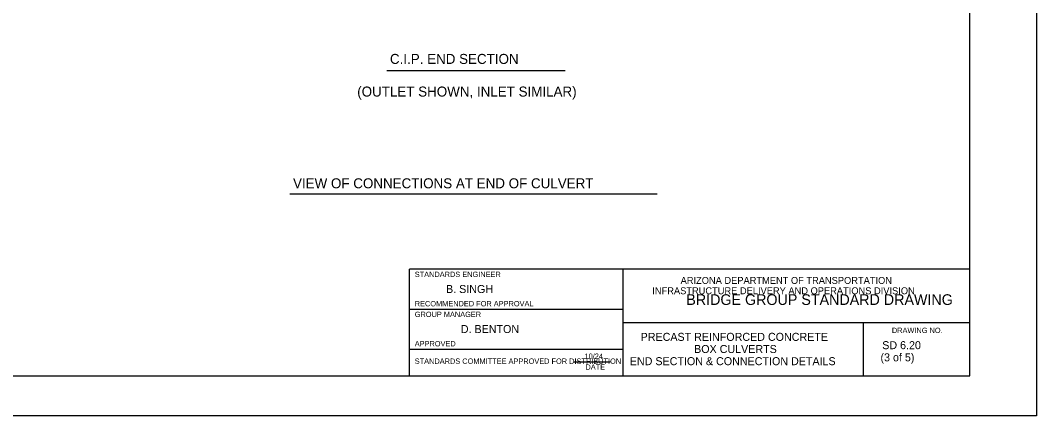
# Model space of a CAD drawing. Extents: x 0 to 2.83, y -0.03 to 1.83.
# Drawn here: x 1.247 to 2.833, y 0 to 0.618 of the extents above; entities that cross this region are included whole.
import ezdxf

# ---------------------------------------------------------------- set-up
doc = ezdxf.new("R2010")
doc.units = 0
for name, color, linetype in [('62', 7, 'Continuous'), ('63', 7, 'Continuous'), ('Default', 7, 'Continuous')]:
    doc.layers.add(name, color=color, linetype=linetype)

msp = doc.modelspace()

# ---------------------------------------------------------------- linework, layer by layer
at = {"layer": '62'}
for p, q in [((1.8542, 0.0624), (1.8542, 0.2291)), ((2.7292, 0.2291), (1.8542, 0.2291)), ((2.1875, 0.2291), (2.1875, 0.0624)), ((2.5625, 0.1458), (2.5625, 0.0624)), ((2.111, 0.0843), (2.1675, 0.0843))]:
    msp.add_line(p, q, dxfattribs=at)
at = {"layer": '63'}
for p, q in [((2.8333, 1.8333), (2.8333, 0)), ((1.8542, 0.1666), (2.1875, 0.1666)), ((2.1875, 0.1458), (2.7292, 0.1458)), ((1.8542, 0.1041), (2.1875, 0.1041)), ((2.8333, 0), (0, 0))]:
    msp.add_line(p, q, dxfattribs=at)
msp.add_lwpolyline([(2.7292, 1.7708), (0.1042, 1.7708), (0.1042, 0.0624), (2.7292, 0.0624)], close=True, dxfattribs=at)
at = {"layer": 'Default'}
for p, q in [((1.8189, 0.539), (2.0975, 0.539)), ((1.6673, 0.3464), (2.2409, 0.3464))]:
    msp.add_line(p, q, dxfattribs=at)

# ---------------------------------------------------------------- texts
at = {"layer": '62'}
for s, height, p in [('STANDARDS ENGINEER', 0.008333, (1.8625, 0.2166)), ('ARIZONA DEPARTMENT OF TRANSPORTATION', 0.010833, (2.2775, 0.2059)), ('      B. SINGH     ', 0.0125, (1.8835, 0.1916)), ('INFRASTRUCTURE DELIVERY AND OPERATIONS DIVISION', 0.010833, (2.2333, 0.1897)), ('RECOMMENDED FOR APPROVAL', 0.008333, (1.8625, 0.1708)), ('BRIDGE GROUP STANDARD DRAWING', 0.016667, (2.2864, 0.173)), ('GROUP MANAGER', 0.008333, (1.8625, 0.1541)), ('D. BENTON   ', 0.0125, (1.9344, 0.1291)), ('PRECAST REINFORCED CONCRETE ', 0.0125, (2.2151, 0.1169)), ('DRAWING NO.', 0.008333, (2.6073, 0.1291)), ('APPROVED', 0.00833, (1.8625, 0.1083)), ('   SD 6.20  ', 0.0125, (2.5783, 0.1039)), ('10/24', 0.00833, (2.1276, 0.0888)), (' BOX CULVERTS ', 0.0125, (2.2939, 0.0979)), ('   (3 of 5)  ', 0.0125, (2.5756, 0.0849)), ('STANDARDS COMMITTEE APPROVED FOR DISTRIBUTION', 0.008333, (1.8625, 0.081)), ('DATE', 0.00833, (2.129, 0.0718)), ('END SECTION & CONNECTION DETAILS', 0.0125, (2.1982, 0.0789))]:
    msp.add_text(s, height=height, dxfattribs=at).set_placement(p)
at = {"layer": 'Default'}
for s, p in [('C.I.P. END SECTION', (1.8238, 0.5495)), ('(OUTLET SHOWN, INLET SIMILAR)', (1.7727, 0.4985)), ('VIEW OF CONNECTIONS AT END OF CULVERT', (1.6725, 0.3552))]:
    msp.add_text(s, height=0.015625, dxfattribs=at).set_placement(p)

doc.saveas('drawing.dxf')
